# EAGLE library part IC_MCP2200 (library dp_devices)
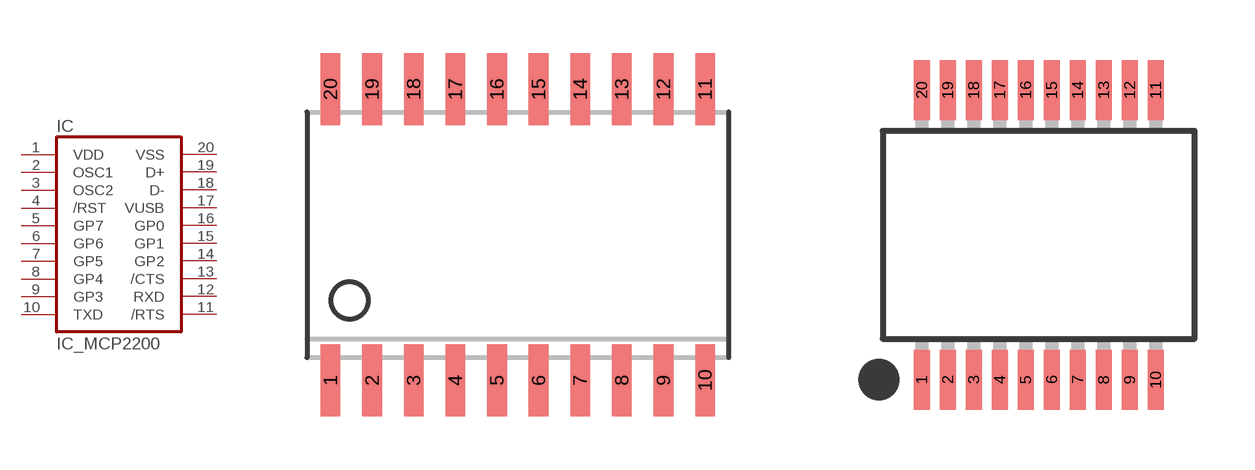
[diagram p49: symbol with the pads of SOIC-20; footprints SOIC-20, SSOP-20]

Designator prefix IC

## IC_MCP2200-SOIC-20  [SOIC-20]
1  VDD
2  OSC1
3  OSC2
4  /RST
5  GP7
6  GP6
7  GP5
8  GP4
9  GP3
10  TXD
11  /RTS
12  RXD
13  /CTS
14  GP2
15  GP1
16  GP0
17  VUSB
18  D-
19  D+
20  VSS

## IC_MCP2200-SSOP-20  [SSOP-20]
Pads as for SOIC-20

## IC_MCP2200-QFN-25-5X5  [QFN25_5X5]
1  /RST
2  GP7
3  GP6
4  GP5
5  GP4
6  GP3
7  TXD
8  /RTS
9  RXD
10  /CTS
11  GP2
12  GP1
13  GP0
14  VUSB
15  D-
16  D+
17  VSS
18  VDD
19  OSC1
20  OSC2

## Footprint SOIC-20 (pad centres in mm)
smd 0.6 x 2.2: 1 -5.715,-4.445; 2 -4.445,-4.445; 3 -3.175,-4.445; 4 -1.905,-4.445; 5 -0.635,-4.445; 6 0.635,-4.445; 7 1.905,-4.445; 8 3.175,-4.445; 9 4.445,-4.445; 10 5.715,-4.445; 11 5.715,4.445; 12 4.445,4.445; 13 3.175,4.445; 14 1.905,4.445; 15 0.635,4.445; 16 -0.635,4.445; 17 -1.905,4.445; 18 -3.175,4.445; 19 -4.445,4.445; 20 -5.715,4.445

## Footprint SSOP-20 (pad centres in mm)
smd 0.4 x 1.5: 1 -2.925,-3.625; 2 -2.275,-3.625; 3 -1.625,-3.625; 4 -0.975,-3.625; 5 -0.325,-3.625; 6 0.325,-3.625; 7 0.975,-3.625; 8 1.625,-3.625; 9 2.275,-3.625; 10 2.925,-3.625; 11 2.925,3.625; 12 2.275,3.625; 13 1.625,3.625; 14 0.975,3.625; 15 0.325,3.625; 16 -0.325,3.625; 17 -0.975,3.625; 18 -1.625,3.625; 19 -2.275,3.625; 20 -2.925,3.625

## Footprint QFN25_5X5 (pad centres in mm)
smd 0.55 x 0.4: 1 -2.275,1.3; 2 -2.275,0.65; 3 -2.275,0; 4 -2.275,-0.65; 5 -2.275,-1.3; 11 2.275,-1.3; 12 2.275,-0.65; 13 2.275,0; 14 2.275,0.65; 15 2.275,1.3
smd 0.4 x 0.55: 6 -1.3,-2.275; 7 -0.65,-2.275; 8 0,-2.275; 9 0.65,-2.275; 10 1.3,-2.275; 16 1.3,2.275; 17 0.65,2.275; 18 0,2.275; 19 -0.65,2.275; 20 -1.3,2.275
drill 0.8 square: P$1 0,0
